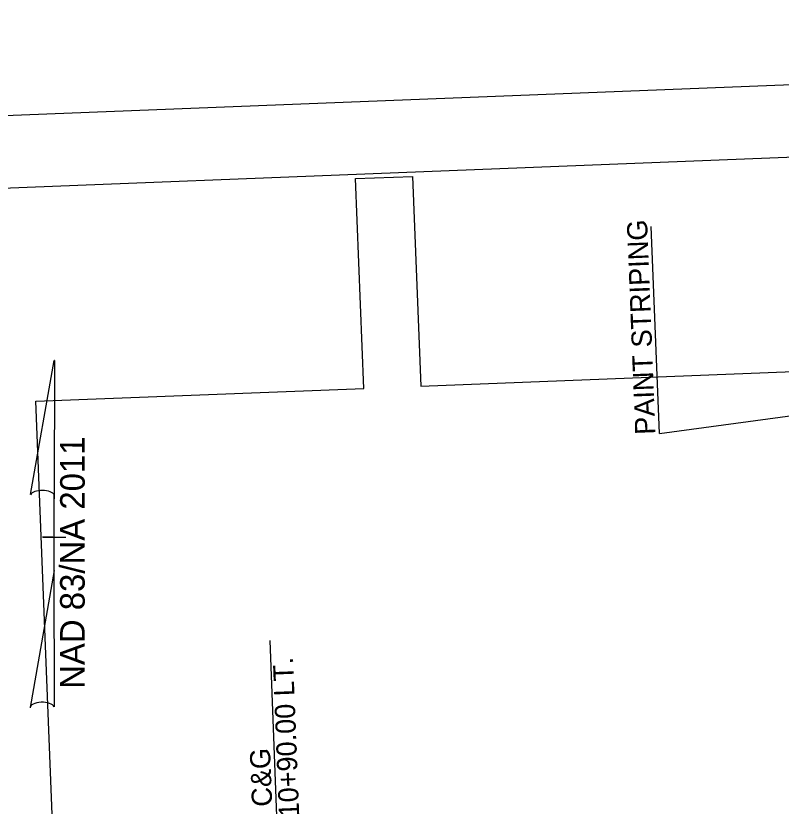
# Model space of a CAD drawing. Extents: x 1627811 to 1628977, y 762656 to 764629.
# Drawn here: x 1628036.7 to 1628300.9, y 764124.9 to 764398 of the extents above; entities that cross this region are included whole.
import ezdxf

# ---------------------------------------------------------------- set-up
doc = ezdxf.new("R2010")
doc.units = 0
for name, color, linetype in [('Prop Dimension', 7, 'Continuous'), ('Prop Dimension Text', 7, 'Continuous'), ('Prop DSN Text', 7, 'Continuous'), ('Prop North Arrow NAD83 for Plan Sheets CELL', 7, 'Continuous'), ('Sheet Clip Boundary CELL', 7, 'Continuous'), ('Sheet Plan And Profile CELL', 7, 'Continuous'), ('Sheet Plot Border Outside CELL', 7, 'Continuous')]:
    doc.layers.add(name, color=color, linetype=linetype)

msp = doc.modelspace()

# ---------------------------------------------------------------- linework, layer by layer
at = {"layer": 'Prop Dimension'}
for p, q in [((1628258.89, 764253.65), (1628256.07, 764325.23)), ((1628258.89, 764253.65), (1628389.33, 764271.55)), ((1628128.8, 764071.76), (1628124.45, 764182.17))]:
    msp.add_line(p, q, dxfattribs=at)
at = {"layer": 'Prop North Arrow NAD83 for Plan Sheets CELL'}
for p, q in [((1628041.71, 764232.55), (1628049.93, 764278.9)), ((1628049.98, 764278.9), (1628049.93, 764278.9)), ((1628049.98, 764278.9), (1628049.93, 764278.9)), ((1628049.98, 764278.9), (1628049.96, 764231.1)), ((1628049.95, 764206.3), (1628049.96, 764232.5)), ((1628049.96, 764231.1), (1628049.96, 764232.45)), ((1628045.95, 764217.9), (1628045.9, 764217.9)), ((1628049.5, 764217.9), (1628045.95, 764217.9)), ((1628046, 764217.9), (1628054, 764217.89)), ((1628049.95, 764206.3), (1628041.58, 764159.05)), ((1628049.98, 764159.25), (1628049.95, 764206.3))]:
    msp.add_line(p, q, dxfattribs=at)
for centre, start_param, end_param in [((1628045.85, 764232.05), 0.216388, 2.908219), ((1628045.81, 764158.88), 0.201328, 3.141593)]:
    msp.add_ellipse(centre, major_axis=(4.23, -0.03), ratio=0.461098, start_param=start_param, end_param=end_param, dxfattribs=at)
at = {"layer": 'Sheet Clip Boundary CELL'}
msp.add_lwpolyline([(1628323.41, 763654.34), (1628302.22, 763717.7), (1628208.23, 763732.1), (1628213.32, 763650), (1628196.97, 763631.82), (1628183.33, 763633.23), (1628068.1, 763644.27), (1628043.63, 764264.81), (1628156.85, 764269.28), (1628154, 764341.74), (1628173.63, 764342.52), (1628176.48, 764270.05), (1628545.1, 764284.59), (1628542.3, 764355.48), (1628560.15, 764356.18), (1628562.95, 764285.29), (1628672.78, 764289.62), (1628669.92, 764362.09), (1628787.91, 764366.75), (1628790.42, 764303.08), (1628811.34, 764303.9), (1628836.16, 763674.56)], close=True, dxfattribs=at)
at = {"layer": 'Sheet Plan And Profile CELL'}
msp.add_lwpolyline([(1627836.47, 764330.65), (1627895.58, 762831.81), (1628944.76, 762873.18), (1628885.66, 764372.02)], close=True, dxfattribs=at)
at = {"layer": 'Sheet Plot Border Outside CELL'}
msp.add_lwpolyline([(1628976.64, 762699.3), (1628909.65, 764397.98), (1627810.51, 764354.64), (1627877.49, 762655.96)], close=True, dxfattribs=at)

# ---------------------------------------------------------------- texts
at = {"layer": 'Prop Dimension Text'}
for s, p in [('-Y14- STA. 10+90.00 LT.', (1628136.49, 764072.32)), ('BEGIN 2\'-6" C&G', (1628127.32, 764071.95))]:
    msp.add_text(s, height=7, rotation=92.2582, dxfattribs=at).set_placement(p)
at = {"layer": 'Prop DSN Text'}
msp.add_text('PAINT STRIPING', height=7, rotation=92.2582, dxfattribs=at).set_placement((1628257.56, 764253.4))
at = {"layer": 'Prop North Arrow NAD83 for Plan Sheets CELL'}
msp.add_text('NAD 83/NA 2011', height=8.5, rotation=89.9757, dxfattribs=at).set_placement((1628060.45, 764165.46))

doc.saveas('drawing.dxf')
